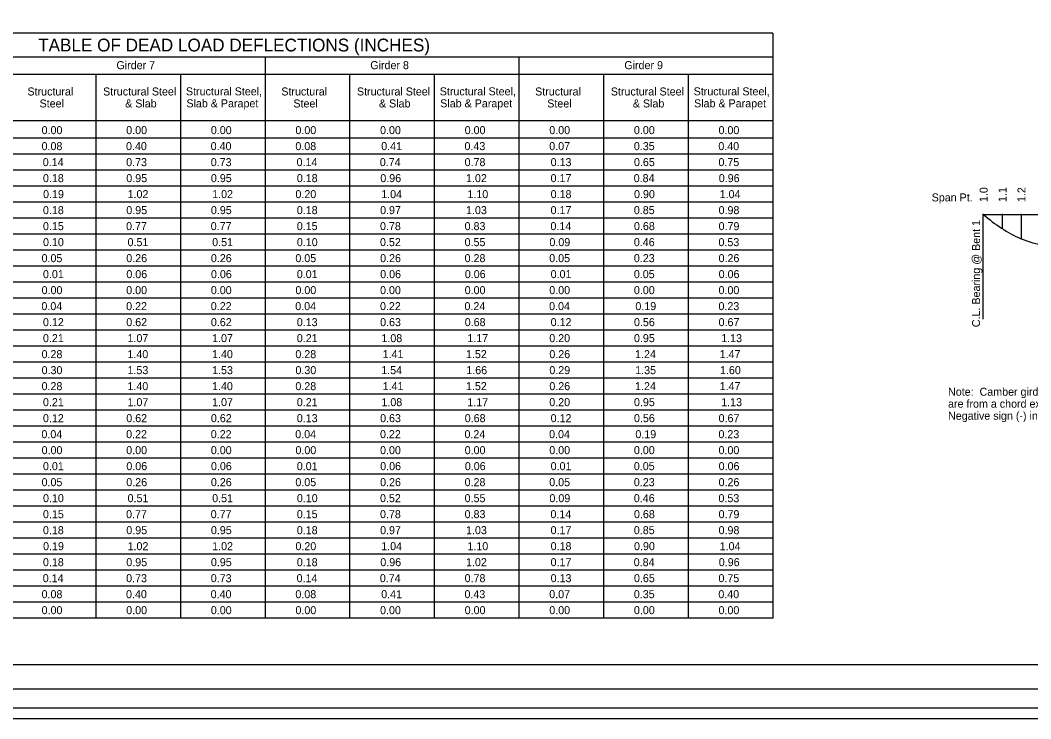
# Model space of a CAD drawing. Extents: x 208.5 to 250.5, y 328.7 to 350.7.
# Drawn here: x 216.62 to 232.41, y 328.74 to 339.65 of the extents above; entities that cross this region are included whole.
import ezdxf

# ---------------------------------------------------------------- set-up
doc = ezdxf.new("R2010")
doc.units = 0
for name, color, linetype in [('border', 7, 'Continuous'), ('Border 2660-Hwy18 - Level 62', 7, 'Continuous'), ('Border 2660-Hwy18 - Level 63', 7, 'Continuous'), ('Dimensions', 7, 'Continuous'), ('Level 20', 7, 'Continuous'), ('Level 25', 7, 'Continuous'), ('Level 40', 7, 'Continuous'), ('Level 41', 7, 'Continuous'), ('Level 62 PDF', 7, 'Continuous'), ('Steel', 7, 'Continuous'), ('Text', 7, 'Continuous'), ('Title Text', 7, 'Continuous')]:
    doc.layers.add(name, color=color, linetype=linetype)

msp = doc.modelspace()

# ---------------------------------------------------------------- linework, layer by layer
at = {"layer": 'border'}
msp.add_line((242.291, 329.584), (210.28, 329.584), dxfattribs=at)
at = {"layer": 'Border 2660-Hwy18 - Level 62'}
msp.add_lwpolyline([(208.659, 350.715), (242.778, 350.715), (242.778, 328.905), (208.659, 328.905)], close=True, dxfattribs=at)
at = {"layer": 'Border 2660-Hwy18 - Level 63'}
msp.add_lwpolyline([(208.548, 350.572), (242.548, 350.572), (242.548, 329.202), (208.548, 329.202)], close=True, dxfattribs=at)
at = {"layer": 'Dimensions'}
for centre in [(231.669, 336.619), (231.965, 336.619), (232.26, 336.619)]:
    msp.add_circle(centre, 0.004, dxfattribs=at)
at = {"layer": 'Level 20'}
msp.add_line((231.669, 334.983), (231.669, 336.619), dxfattribs=at)
at = {"layer": 'Level 25'}
msp.add_line((231.669, 336.619), (234.624, 336.619), dxfattribs=at)
at = {"layer": 'Level 41'}
for p, q in [((231.965, 336.619), (231.965, 336.398)), ((232.26, 336.619), (232.26, 336.239))]:
    msp.add_line(p, q, dxfattribs=at)
msp.add_open_spline([(231.671, 336.619), (231.764, 336.538), (231.952, 336.398), (232.247, 336.228), (232.641, 336.12), (232.928, 336.094), (233.215, 336.172), (233.607, 336.276), (233.972, 336.459), (234.129, 336.511), (234.285, 336.564), (234.524, 336.615), (234.624, 336.618)], degree=3, dxfattribs=at)
at = {"layer": 'Level 62 PDF'}
msp.add_lwpolyline([(208.909, 350.548), (243.028, 350.548), (243.028, 328.739), (208.909, 328.739)], close=True, dxfattribs=at)
at = {"layer": 'Steel'}
for p, q in [((228.381, 339.452), (210.932, 339.452)), ((228.381, 339.452), (228.381, 330.311)), ((228.381, 339.075), (210.932, 339.075)), ((220.449, 339.075), (220.449, 330.311)), ((224.415, 339.075), (224.415, 330.311)), ((228.381, 338.806), (212.517, 338.806)), ((217.805, 338.806), (217.805, 330.311)), ((219.127, 338.806), (219.127, 330.311)), ((221.771, 338.806), (221.771, 330.311)), ((223.093, 338.806), (223.093, 330.311)), ((225.737, 338.806), (225.737, 330.311)), ((227.059, 338.806), (227.059, 330.311)), ((228.381, 338.08), (210.932, 338.08)), ((228.381, 337.811), (211.725, 337.811)), ((228.381, 337.561), (211.725, 337.561)), ((228.381, 337.311), (211.725, 337.311)), ((228.381, 337.061), (211.725, 337.061)), ((228.381, 336.811), (211.725, 336.811)), ((228.381, 336.561), (211.725, 336.561)), ((228.381, 336.311), (211.725, 336.311)), ((228.381, 336.061), (211.725, 336.061)), ((228.381, 335.811), (211.725, 335.811)), ((228.381, 335.561), (211.725, 335.561)), ((228.381, 335.311), (211.725, 335.311)), ((228.381, 335.061), (211.725, 335.061)), ((228.381, 334.811), (211.725, 334.811)), ((228.381, 334.561), (211.725, 334.561)), ((228.381, 334.311), (211.725, 334.311)), ((228.381, 334.061), (211.725, 334.061)), ((228.381, 333.811), (211.725, 333.811)), ((228.381, 333.561), (211.725, 333.561)), ((228.381, 333.311), (211.725, 333.311)), ((228.381, 333.061), (211.725, 333.061)), ((228.381, 332.811), (211.725, 332.811)), ((228.381, 332.561), (211.725, 332.561)), ((228.381, 332.311), (211.725, 332.311)), ((228.381, 332.061), (211.725, 332.061)), ((228.381, 331.811), (211.725, 331.811)), ((228.381, 331.561), (211.725, 331.561)), ((228.381, 331.311), (211.725, 331.311)), ((228.381, 331.061), (211.725, 331.061)), ((228.381, 330.811), (211.725, 330.811)), ((228.381, 330.561), (211.725, 330.561)), ((228.381, 330.311), (210.932, 330.311))]:
    msp.add_line(p, q, dxfattribs=at)

# ---------------------------------------------------------------- texts
at = {"layer": 'Level 40'}
for s, height, rotation, p in [('Span Pt.', 0.125, 359.9998, (230.864, 336.822)), ('1.0', 0.125, 89.9998, (231.739, 336.812)), ('1.1', 0.125, 89.9998, (232.034, 336.812)), ('1.2', 0.125, 89.9998, (232.33, 336.812)), ('C.L. Bearing @ Bent 1', 0.12501, 89.9998, (231.62, 334.857))]:
    msp.add_text(s, height=height, rotation=rotation, dxfattribs=at).set_placement(p)
for s, p in [('Note:  Camber girders for dead load deflection plus vertical curve and superelevation transition. Tolerance is È 1/4". Deflections shown', (231.12, 333.786)), ('are from a chord extending from C.L. Bearing to C.L. Bearing. Vertical curve corrections and superelevation transition are not included.', (231.12, 333.599)), ('Negative sign (-) indicates point above chord.', (231.12, 333.411))]:
    msp.add_text(s, height=0.125, dxfattribs=at).set_placement(p)
at = {"layer": 'Text'}
for s, p in [('Girder 7', (218.127, 338.888)), ('Girder 8', (222.093, 338.888)), ('Girder 9', (226.062, 338.888)), ('Structural', (216.737, 338.477)), ('Structural Steel', (217.919, 338.477)), ('Structural Steel,', (219.213, 338.479)), ('Structural', (220.703, 338.477)), ('Structural Steel', (221.885, 338.477)), ('Structural Steel,', (223.179, 338.479)), ('Structural', (224.669, 338.477)), ('Structural Steel', (225.851, 338.477)), ('Structural Steel,', (227.145, 338.479)), ('Steel', (216.926, 338.29)), ('& Slab', (218.263, 338.29)), ('Slab & Parapet', (219.22, 338.292)), ('Steel', (220.892, 338.29)), ('& Slab', (222.229, 338.29)), ('Slab & Parapet', (223.186, 338.292)), ('Steel', (224.858, 338.29)), ('& Slab', (226.195, 338.29)), ('Slab & Parapet', (227.152, 338.292)), ('0.00', (216.958, 337.873)), ('0.00', (218.28, 337.873)), ('0.00', (219.602, 337.873)), ('0.00', (220.924, 337.873)), ('0.00', (222.246, 337.873)), ('0.00', (223.568, 337.873)), ('0.00', (224.89, 337.873)), ('0.00', (226.212, 337.873)), ('0.00', (227.534, 337.873)), ('0.08', (216.957, 337.623)), ('0.40', (218.277, 337.623)), ('0.40', (219.599, 337.623)), ('0.08', (220.923, 337.623)), ('0.41', (222.264, 337.623)), ('0.43', (223.565, 337.623)), ('0.07', (224.889, 337.623)), ('0.35', (226.211, 337.623)), ('0.40', (227.531, 337.623)), ('0.14', (216.976, 337.373)), ('0.73', (218.279, 337.373)), ('0.73', (219.601, 337.373)), ('0.14', (220.942, 337.373)), ('0.74', (222.242, 337.373)), ('0.78', (223.567, 337.373)), ('0.13', (224.911, 337.373)), ('0.65', (226.213, 337.373)), ('0.75', (227.533, 337.373)), ('0.18', (216.979, 337.123)), ('0.95', (218.281, 337.123)), ('0.95', (219.603, 337.123)), ('0.18', (220.945, 337.123)), ('0.96', (222.25, 337.123)), ('1.02', (223.589, 337.123)), ('0.17', (224.91, 337.123)), ('0.84', (226.209, 337.123)), ('0.96', (227.538, 337.123)), ('0.19', (216.981, 336.873)), ('1.02', (218.301, 336.873)), ('1.02', (219.623, 336.873)), ('0.20', (220.924, 336.873)), ('1.04', (222.264, 336.873)), ('1.10', (223.611, 336.873)), ('0.18', (224.911, 336.873)), ('0.90', (226.214, 336.873)), ('1.04', (227.552, 336.873)), ('0.18', (216.979, 336.623)), ('0.95', (218.281, 336.623)), ('0.95', (219.603, 336.623)), ('0.18', (220.945, 336.623)), ('0.97', (222.247, 336.623)), ('1.03', (223.589, 336.623)), ('0.17', (224.91, 336.623)), ('0.85', (226.211, 336.623)), ('0.98', (227.535, 336.623)), ('0.15', (216.979, 336.373)), ('0.77', (218.278, 336.373)), ('0.77', (219.6, 336.373)), ('0.15', (220.945, 336.373)), ('0.78', (222.245, 336.373)), ('0.83', (223.567, 336.373)), ('0.14', (224.908, 336.373)), ('0.68', (226.213, 336.373)), ('0.79', (227.535, 336.373)), ('0.10', (216.98, 336.123)), ('0.51', (218.301, 336.123)), ('0.51', (219.623, 336.123)), ('0.10', (220.946, 336.123)), ('0.52', (222.245, 336.123)), ('0.55', (223.567, 336.123)), ('0.09', (224.892, 336.123)), ('0.46', (226.211, 336.123)), ('0.53', (227.533, 336.123)), ('0.05', (216.957, 335.873)), ('0.26', (218.281, 335.873)), ('0.26', (219.603, 335.873)), ('0.05', (220.923, 335.873)), ('0.26', (222.247, 335.873)), ('0.28', (223.567, 335.873)), ('0.05', (224.889, 335.873)), ('0.23', (226.211, 335.873)), ('0.26', (227.535, 335.873)), ('0.01', (216.979, 335.623)), ('0.06', (218.282, 335.623)), ('0.06', (219.604, 335.623)), ('0.01', (220.945, 335.623)), ('0.06', (222.248, 335.623)), ('0.06', (223.57, 335.623)), ('0.01', (224.911, 335.623)), ('0.05', (226.211, 335.623)), ('0.06', (227.536, 335.623)), ('0.00', (216.958, 335.373)), ('0.00', (218.28, 335.373)), ('0.00', (219.602, 335.373)), ('0.00', (220.924, 335.373)), ('0.00', (222.246, 335.373)), ('0.00', (223.568, 335.373)), ('0.00', (224.89, 335.373)), ('0.00', (226.212, 335.373)), ('0.00', (227.534, 335.373)), ('0.04', (216.955, 335.123)), ('0.22', (218.279, 335.123)), ('0.22', (219.601, 335.123)), ('0.04', (220.921, 335.123)), ('0.22', (222.245, 335.123)), ('0.24', (223.565, 335.123)), ('0.04', (224.887, 335.123)), ('0.19', (226.235, 335.123)), ('0.23', (227.533, 335.123)), ('0.12', (216.979, 334.873)), ('0.62', (218.281, 334.873)), ('0.62', (219.603, 334.873)), ('0.13', (220.945, 334.873)), ('0.63', (222.247, 334.873)), ('0.68', (223.569, 334.873)), ('0.12', (224.911, 334.873)), ('0.56', (226.213, 334.873)), ('0.67', (227.535, 334.873)), ('0.21', (216.979, 334.623)), ('1.07', (218.3, 334.623)), ('1.07', (219.622, 334.623)), ('0.21', (220.945, 334.623)), ('1.08', (222.267, 334.623)), ('1.17', (223.609, 334.623)), ('0.20', (224.89, 334.623)), ('0.95', (226.213, 334.623)), ('1.13', (227.576, 334.623)), ('0.28', (216.957, 334.373)), ('1.40', (218.299, 334.373)), ('1.40', (219.621, 334.373)), ('0.28', (220.923, 334.373)), ('1.41', (222.286, 334.373)), ('1.52', (223.588, 334.373)), ('0.26', (224.891, 334.373)), ('1.24', (226.23, 334.373)), ('1.47', (227.551, 334.373)), ('0.30', (216.958, 334.123)), ('1.53', (218.3, 334.123)), ('1.53', (219.622, 334.123)), ('0.30', (220.924, 334.123)), ('1.54', (222.264, 334.123)), ('1.66', (223.593, 334.123)), ('0.29', (224.891, 334.123)), ('1.35', (226.232, 334.123)), ('1.60', (227.557, 334.123)), ('0.28', (216.957, 333.873)), ('1.40', (218.299, 333.873)), ('1.40', (219.621, 333.873)), ('0.28', (220.923, 333.873)), ('1.41', (222.286, 333.873)), ('1.52', (223.588, 333.873)), ('0.26', (224.891, 333.873)), ('1.24', (226.23, 333.873)), ('1.47', (227.551, 333.873)), ('0.21', (216.979, 333.623)), ('1.07', (218.3, 333.623)), ('1.07', (219.622, 333.623)), ('0.21', (220.945, 333.623)), ('1.08', (222.267, 333.623)), ('1.17', (223.609, 333.623)), ('0.20', (224.89, 333.623)), ('0.95', (226.213, 333.623)), ('1.13', (227.576, 333.623)), ('0.12', (216.979, 333.373)), ('0.62', (218.281, 333.373)), ('0.62', (219.603, 333.373)), ('0.13', (220.945, 333.373)), ('0.63', (222.247, 333.373)), ('0.68', (223.569, 333.373)), ('0.12', (224.911, 333.373)), ('0.56', (226.213, 333.373)), ('0.67', (227.535, 333.373)), ('0.04', (216.955, 333.123)), ('0.22', (218.279, 333.123)), ('0.22', (219.601, 333.123)), ('0.04', (220.921, 333.123)), ('0.22', (222.245, 333.123)), ('0.24', (223.565, 333.123)), ('0.04', (224.887, 333.123)), ('0.19', (226.235, 333.123)), ('0.23', (227.533, 333.123)), ('0.00', (216.958, 332.873)), ('0.00', (218.28, 332.873)), ('0.00', (219.602, 332.873)), ('0.00', (220.924, 332.873)), ('0.00', (222.246, 332.873)), ('0.00', (223.568, 332.873)), ('0.00', (224.89, 332.873)), ('0.00', (226.212, 332.873)), ('0.00', (227.534, 332.873)), ('0.01', (216.979, 332.623)), ('0.06', (218.282, 332.623)), ('0.06', (219.604, 332.623)), ('0.01', (220.945, 332.623)), ('0.06', (222.248, 332.623)), ('0.06', (223.57, 332.623)), ('0.01', (224.911, 332.623)), ('0.05', (226.211, 332.623)), ('0.06', (227.536, 332.623)), ('0.05', (216.957, 332.373)), ('0.26', (218.281, 332.373)), ('0.26', (219.603, 332.373)), ('0.05', (220.923, 332.373)), ('0.26', (222.247, 332.373)), ('0.28', (223.567, 332.373)), ('0.05', (224.889, 332.373)), ('0.23', (226.211, 332.373)), ('0.26', (227.535, 332.373)), ('0.10', (216.98, 332.123)), ('0.51', (218.301, 332.123)), ('0.51', (219.623, 332.123)), ('0.10', (220.946, 332.123)), ('0.52', (222.245, 332.123)), ('0.55', (223.567, 332.123)), ('0.09', (224.892, 332.123)), ('0.46', (226.211, 332.123)), ('0.53', (227.533, 332.123)), ('0.15', (216.979, 331.873)), ('0.77', (218.278, 331.873)), ('0.77', (219.6, 331.873)), ('0.15', (220.945, 331.873)), ('0.78', (222.245, 331.873)), ('0.83', (223.567, 331.873)), ('0.14', (224.908, 331.873)), ('0.68', (226.213, 331.873)), ('0.79', (227.535, 331.873)), ('0.18', (216.979, 331.623)), ('0.95', (218.281, 331.623)), ('0.95', (219.603, 331.623)), ('0.18', (220.945, 331.623)), ('0.97', (222.247, 331.623)), ('1.03', (223.589, 331.623)), ('0.17', (224.91, 331.623)), ('0.85', (226.211, 331.623)), ('0.98', (227.535, 331.623)), ('0.19', (216.981, 331.373)), ('1.02', (218.301, 331.373)), ('1.02', (219.623, 331.373)), ('0.20', (220.924, 331.373)), ('1.04', (222.264, 331.373)), ('1.10', (223.611, 331.373)), ('0.18', (224.911, 331.373)), ('0.90', (226.214, 331.373)), ('1.04', (227.552, 331.373)), ('0.18', (216.979, 331.123)), ('0.95', (218.281, 331.123)), ('0.95', (219.603, 331.123)), ('0.18', (220.945, 331.123)), ('0.96', (222.25, 331.123)), ('1.02', (223.589, 331.123)), ('0.17', (224.91, 331.123)), ('0.84', (226.209, 331.123)), ('0.96', (227.538, 331.123)), ('0.14', (216.976, 330.873)), ('0.73', (218.279, 330.873)), ('0.73', (219.601, 330.873)), ('0.14', (220.942, 330.873)), ('0.74', (222.242, 330.873)), ('0.78', (223.567, 330.873)), ('0.13', (224.911, 330.873)), ('0.65', (226.213, 330.873)), ('0.75', (227.533, 330.873)), ('0.08', (216.957, 330.623)), ('0.40', (218.277, 330.623)), ('0.40', (219.599, 330.623)), ('0.08', (220.923, 330.623)), ('0.41', (222.264, 330.623)), ('0.43', (223.565, 330.623)), ('0.07', (224.889, 330.623)), ('0.35', (226.211, 330.623)), ('0.40', (227.531, 330.623)), ('0.00', (216.958, 330.373)), ('0.00', (218.28, 330.373)), ('0.00', (219.602, 330.373)), ('0.00', (220.924, 330.373)), ('0.00', (222.246, 330.373)), ('0.00', (223.568, 330.373)), ('0.00', (224.89, 330.373)), ('0.00', (226.212, 330.373)), ('0.00', (227.534, 330.373))]:
    msp.add_text(s, height=0.125, dxfattribs=at).set_placement(p)
at = {"layer": 'Title Text'}
msp.add_text('TABLE OF DEAD LOAD DEFLECTIONS (INCHES)', height=0.2, dxfattribs=at).set_placement((216.904, 339.165))

doc.saveas('drawing.dxf')
